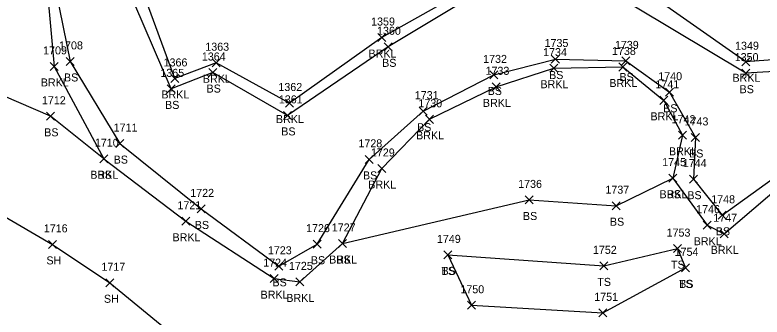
# Model space of a CAD drawing. Extents: x 1754529 to 1755810, y 621660 to 624656.
# Drawn here: x 1755027.6 to 1755214.3, y 623873.5 to 623948.9 of the extents above; entities that cross this region are included whole.
import ezdxf

# ---------------------------------------------------------------- set-up
doc = ezdxf.new("R2010")
doc.units = 0
for name, color, linetype in [('L_A', 7, 'Continuous'), ('L_I', 7, 'Continuous'), ('L_TIC', 7, 'Continuous'), ('LAWE', 7, 'Continuous'), ('LELB', 7, 'Continuous'), ('LSOGP', 7, 'Continuous')]:
    doc.layers.add(name, color=color, linetype=linetype)

msp = doc.modelspace()

# ---------------------------------------------------------------- linework, layer by layer
at = {"layer": 'L_TIC'}
for points in [[(1755118.33, 623942.27), (1755120.33, 623944.27)], [(1755120.33, 623942.27), (1755118.33, 623944.27)], [(1755119.93, 623939.96), (1755121.93, 623941.96)], [(1755121.93, 623939.96), (1755119.93, 623941.96)], [(1755040.45, 623936.31), (1755042.45, 623938.31)], [(1755042.45, 623936.31), (1755040.45, 623938.31)], [(1755076.94, 623935.98), (1755078.94, 623937.98)], [(1755078.94, 623935.98), (1755076.94, 623937.98)], [(1755161.66, 623936.91), (1755163.66, 623938.91)], [(1755163.66, 623936.91), (1755161.66, 623938.91)], [(1755179.24, 623936.43), (1755181.24, 623938.43)], [(1755181.24, 623936.43), (1755179.24, 623938.43)], [(1755209.27, 623936.23), (1755211.27, 623938.23)], [(1755211.27, 623936.23), (1755209.27, 623938.23)], [(1755036.46, 623935.07), (1755038.46, 623937.07)], [(1755038.46, 623935.07), (1755036.46, 623937.07)], [(1755076.07, 623933.54), (1755078.07, 623935.54)], [(1755078.07, 623933.54), (1755076.07, 623935.54)], [(1755161.29, 623934.63), (1755163.29, 623936.63)], [(1755163.29, 623934.63), (1755161.29, 623936.63)], [(1755178.51, 623934.92), (1755180.51, 623936.92)], [(1755180.51, 623934.92), (1755178.51, 623936.92)], [(1755209.26, 623933.38), (1755211.26, 623935.38)], [(1755211.26, 623933.38), (1755209.26, 623935.38)], [(1755066.58, 623932.06), (1755068.58, 623934.06)], [(1755068.58, 623932.06), (1755066.58, 623934.06)], [(1755146.31, 623932.94), (1755148.31, 623934.94)], [(1755148.31, 623932.94), (1755146.31, 623934.94)], [(1755146.91, 623929.97), (1755148.91, 623931.97)], [(1755148.91, 623929.97), (1755146.91, 623931.97)], [(1755065.71, 623929.46), (1755067.71, 623931.46)], [(1755067.71, 623929.46), (1755065.71, 623931.46)], [(1755190.16, 623928.62), (1755192.16, 623930.62)], [(1755192.16, 623928.62), (1755190.16, 623930.62)], [(1755095.2, 623925.93), (1755097.2, 623927.93)], [(1755097.2, 623925.93), (1755095.2, 623927.93)], [(1755188.79, 623926.6), (1755190.79, 623928.6)], [(1755190.79, 623926.6), (1755188.79, 623928.6)], [(1755035.51, 623922.62), (1755037.51, 623924.62)], [(1755037.51, 623922.62), (1755035.51, 623924.62)], [(1755094.74, 623922.84), (1755096.74, 623924.84)], [(1755096.74, 623922.84), (1755094.74, 623924.84)], [(1755128.67, 623923.89), (1755130.67, 623925.89)], [(1755130.67, 623923.89), (1755128.67, 623925.89)], [(1755130.22, 623921.86), (1755132.22, 623923.86)], [(1755132.22, 623921.86), (1755130.22, 623923.86)], [(1755193.4, 623917.88), (1755195.4, 623919.88)], [(1755195.4, 623917.88), (1755193.4, 623919.88)], [(1755196.64, 623917.34), (1755198.64, 623919.34)], [(1755198.64, 623917.34), (1755196.64, 623919.34)], [(1755052.86, 623915.81), (1755054.86, 623917.81)], [(1755054.86, 623915.81), (1755052.86, 623917.81)], [(1755048.82, 623912.03), (1755050.82, 623914.03)], [(1755050.82, 623912.03), (1755048.82, 623914.03)], [(1755048.82, 623912.03), (1755050.82, 623914.03)], [(1755050.82, 623912.03), (1755048.82, 623914.03)], [(1755115.15, 623911.87), (1755117.15, 623913.87)], [(1755117.15, 623911.87), (1755115.15, 623913.87)], [(1755118.28, 623909.59), (1755120.28, 623911.59)], [(1755120.28, 623909.59), (1755118.28, 623911.59)], [(1755191.05, 623907.18), (1755193.05, 623909.18)], [(1755193.05, 623907.18), (1755191.05, 623909.18)], [(1755191.05, 623907.18), (1755193.05, 623909.18)], [(1755193.05, 623907.18), (1755191.05, 623909.18)], [(1755196.2, 623906.93), (1755198.2, 623908.93)], [(1755198.2, 623906.93), (1755196.2, 623908.93)], [(1755155.12, 623901.74), (1755157.12, 623903.74)], [(1755157.12, 623901.74), (1755155.12, 623903.74)], [(1755176.86, 623900.31), (1755178.86, 623902.31)], [(1755178.86, 623900.31), (1755176.86, 623902.31)], [(1755073.13, 623899.5), (1755075.13, 623901.5)], [(1755075.13, 623899.5), (1755073.13, 623901.5)], [(1755203.31, 623897.91), (1755205.31, 623899.91)], [(1755205.31, 623897.91), (1755203.31, 623899.91)], [(1755069.37, 623896.42), (1755071.37, 623898.42)], [(1755071.37, 623896.42), (1755069.37, 623898.42)], [(1755199.59, 623895.44), (1755201.59, 623897.44)], [(1755201.59, 623895.44), (1755199.59, 623897.44)], [(1755203.82, 623893.29), (1755205.82, 623895.29)], [(1755205.82, 623893.29), (1755203.82, 623895.29)], [(1755036.03, 623890.65), (1755038.03, 623892.65)], [(1755038.03, 623890.65), (1755036.03, 623892.65)], [(1755102.13, 623890.7), (1755104.13, 623892.7)], [(1755104.13, 623890.7), (1755102.13, 623892.7)], [(1755108.49, 623890.87), (1755110.49, 623892.87)], [(1755110.49, 623890.87), (1755108.49, 623892.87)], [(1755108.49, 623890.87), (1755110.49, 623892.87)], [(1755110.49, 623890.87), (1755108.49, 623892.87)], [(1755192.16, 623889.59), (1755194.16, 623891.59)], [(1755194.16, 623889.59), (1755192.16, 623891.59)], [(1755134.78, 623888.03), (1755136.78, 623890.03)], [(1755136.78, 623888.03), (1755134.78, 623890.03)], [(1755134.78, 623888.03), (1755136.78, 623890.03)], [(1755136.78, 623888.03), (1755134.78, 623890.03)], [(1755092.54, 623885.18), (1755094.54, 623887.18)], [(1755094.54, 623885.18), (1755092.54, 623887.18)], [(1755173.74, 623885.29), (1755175.74, 623887.29)], [(1755175.74, 623885.29), (1755173.74, 623887.29)], [(1755194.16, 623884.79), (1755196.16, 623886.79)], [(1755196.16, 623884.79), (1755194.16, 623886.79)], [(1755194.16, 623884.79), (1755196.16, 623886.79)], [(1755196.16, 623884.79), (1755194.16, 623886.79)], [(1755050.38, 623881.08), (1755052.38, 623883.08)], [(1755052.38, 623881.08), (1755050.38, 623883.08)], [(1755091.38, 623882.1), (1755093.38, 623884.1)], [(1755093.38, 623882.1), (1755091.38, 623884.1)], [(1755097.8, 623881.29), (1755099.8, 623883.29)], [(1755099.8, 623881.29), (1755097.8, 623883.29)], [(1755140.72, 623875.45), (1755142.72, 623877.45)], [(1755142.72, 623875.45), (1755140.72, 623877.45)], [(1755173.5, 623873.56), (1755175.5, 623875.56)], [(1755175.5, 623873.56), (1755173.5, 623875.56)]]:
    msp.add_lwpolyline(points, dxfattribs=at)
at = {"layer": 'LAWE'}
for points in [[(1755170.6, 623960.85), (1755161.2, 623961.01), (1755143.2, 623956.78), (1755119.33, 623943.27), (1755096.2, 623926.93), (1755077.94, 623936.98), (1755067.58, 623933.06), (1755059.57, 623954.81), (1755059, 623978.5), (1755052.5, 623999.83), (1755039.74, 624025.98), (1755043.94, 624041.32), (1755011.46, 624067.07)], [(1755008.39, 624026.55), (1755031, 623998.61), (1755039.69, 623976.43), (1755035.65, 623955.37), (1755037.46, 623936.07), (1755049.82, 623913.03), (1755070.37, 623897.42), (1755092.38, 623883.1), (1755098.8, 623882.29), (1755109.49, 623891.87), (1755119.28, 623910.59), (1755131.22, 623922.86), (1755147.91, 623930.97), (1755162.29, 623935.63), (1755179.51, 623935.92), (1755189.79, 623927.6), (1755194.4, 623918.88), (1755192.05, 623908.18), (1755200.59, 623896.44), (1755204.82, 623894.29), (1755230.46, 623916.2)], [(1755370.87, 623791.95), (1755363.68, 623808), (1755365.74, 623820.69), (1755355.03, 623846.72), (1755346.68, 623853.51), (1755335.09, 623877.41), (1755323.56, 623896.77), (1755319.21, 623906.81), (1755286.2, 623944.29), (1755265.65, 623945.4), (1755241.6, 623939.51), (1755210.27, 623937.23), (1755179.93, 623958.52)]]:
    msp.add_lwpolyline(points, dxfattribs=at)
at = {"layer": 'LELB'}
for points in [[(1755241.68, 623936.2), (1755210.26, 623934.38), (1755173.74, 623956.25), (1755172.44, 623956.64), (1755160.09, 623957.64), (1755143.35, 623954.54), (1755120.93, 623940.96), (1755095.74, 623923.84), (1755077.07, 623934.54), (1755066.71, 623930.46), (1755055.52, 623956.39), (1755055.45, 623977.68), (1755049.43, 623997.7), (1755037.69, 624026.06), (1755041.22, 624040.25), (1755009.04, 624065.23)], [(1755012.46, 624027.69), (1755032.85, 623998.91), (1755041.63, 623976.49), (1755037.86, 623954.93), (1755041.45, 623937.31), (1755053.86, 623916.81), (1755074.13, 623900.5), (1755093.54, 623886.18), (1755103.13, 623891.7), (1755116.15, 623912.87), (1755129.67, 623924.89), (1755147.31, 623933.94), (1755162.66, 623937.91), (1755180.24, 623937.43), (1755191.16, 623929.62), (1755197.64, 623918.34), (1755197.2, 623907.93), (1755204.31, 623898.91), (1755229.99, 623917.44)], [(1755049.82, 623913.03), (1755036.51, 623923.62), (1754996.89, 623940.7), (1754976.92, 623965.01)], [(1755109.49, 623891.87), (1755156.12, 623902.74), (1755177.86, 623901.31), (1755192.05, 623908.18)], [(1755135.78, 623889.03), (1755174.74, 623886.29), (1755193.16, 623890.59), (1755195.16, 623885.79)], [(1755135.78, 623889.03), (1755141.72, 623876.45), (1755174.5, 623874.56), (1755195.16, 623885.79)]]:
    msp.add_lwpolyline(points, dxfattribs=at)
at = {"layer": 'LSOGP'}
msp.add_lwpolyline([(1755004.07, 623910.86), (1755037.03, 623891.65), (1755051.38, 623882.08), (1755070.03, 623866.74), (1755086.65, 623861.82), (1755098.54, 623857.57), (1755139.32, 623863.34), (1755161.91, 623859.08), (1755179.26, 623858.35), (1755194.19, 623862.7), (1755207.96, 623861.99), (1755217.43, 623865.11), (1755235.99, 623865.05), (1755250.43, 623863.91), (1755263.55, 623860.65), (1755279.26, 623833.69), (1755282.84, 623818.8), (1755283.41, 623777.57), (1755283.62, 623765.66), (1755287.66, 623764.84), (1755327.27, 623772.06), (1755352.63, 623769.93), (1755354.61, 623769.01), (1755434.62, 623771.42)], dxfattribs=at)

# ---------------------------------------------------------------- texts
at = {"layer": 'L_A'}
for s, p in [('BRKL', (1755115.98, 623938.27)), ('BS', (1755119.38, 623935.96)), ('BS', (1755039.89, 623932.31)), ('BRKL', (1755074.59, 623931.98)), ('BS', (1755161.1, 623932.91)), ('BS', (1755178.68, 623932.43)), ('BRKL', (1755206.92, 623932.23)), ('BRKL', (1755034.1, 623931.07)), ('BS', (1755075.51, 623929.54)), ('BRKL', (1755158.94, 623930.63)), ('BRKL', (1755176.16, 623930.92)), ('BRKL', (1755064.22, 623928.06)), ('BS', (1755145.75, 623928.94)), ('BS', (1755208.7, 623929.38)), ('BRKL', (1755144.56, 623925.97)), ('BS', (1755065.15, 623925.46)), ('BS', (1755189.6, 623924.62)), ('BRKL', (1755186.43, 623922.6)), ('BRKL', (1755092.85, 623921.93)), ('BS', (1755034.95, 623918.62)), ('BS', (1755094.18, 623918.84)), ('BS', (1755128.11, 623919.89)), ('BRKL', (1755127.87, 623917.86)), ('BRKL', (1755191.05, 623913.88)), ('BS', (1755196.08, 623913.34)), ('BS', (1755052.3, 623911.81)), ('BRKL', (1755046.47, 623908.03)), ('BS', (1755048.26, 623908.03)), ('BS', (1755114.6, 623907.87)), ('BRKL', (1755115.92, 623905.59)), ('BRKL', (1755188.69, 623903.18)), ('BS', (1755190.49, 623903.18)), ('BS', (1755195.64, 623902.93)), ('BS', (1755154.56, 623897.74)), ('BS', (1755176.3, 623896.31)), ('BS', (1755072.57, 623895.5)), ('BRKL', (1755067.01, 623892.42)), ('BS', (1755202.75, 623893.91)), ('BRKL', (1755197.24, 623891.44)), ('BRKL', (1755201.47, 623889.29)), ('SH', (1755035.51, 623886.65)), ('BS', (1755101.57, 623886.7)), ('BRKL', (1755106.14, 623886.87)), ('BS', (1755107.94, 623886.87)), ('TS', (1755191.57, 623885.59)), ('TS', (1755134.19, 623884.03)), ('BS', (1755134.23, 623884.03)), ('BS', (1755091.98, 623881.18)), ('TS', (1755173.15, 623881.29)), ('TS', (1755193.57, 623880.79)), ('BS', (1755193.6, 623880.79)), ('BRKL', (1755089.02, 623878.1)), ('BRKL', (1755095.44, 623877.29)), ('SH', (1755049.87, 623877.08))]:
    msp.add_text(s, height=2, dxfattribs=at).set_placement(p)
at = {"layer": 'L_I'}
for s, p in [('1359', (1755116.63, 623946.27)), ('1360', (1755118.11, 623943.96)), ('1735', (1755159.97, 623940.91)), ('1709', (1755034.68, 623939.07)), ('1708', (1755038.67, 623940.31)), ('1363', (1755075.2, 623939.98)), ('1738', (1755176.82, 623938.92)), ('1739', (1755177.54, 623940.43)), ('1349', (1755207.57, 623940.23)), ('1364', (1755074.33, 623937.54)), ('1732', (1755144.62, 623936.94)), ('1734', (1755159.6, 623938.63)), ('1350', (1755207.48, 623937.38)), ('1366', (1755064.78, 623936.06)), ('1365', (1755063.97, 623933.46)), ('1733', (1755145.22, 623933.97)), ('1740', (1755188.38, 623932.62)), ('1362', (1755093.46, 623929.93)), ('1741', (1755187.66, 623930.6)), ('1731', (1755127.54, 623927.89)), ('1712', (1755034.38, 623926.62)), ('1361', (1755093.57, 623926.84)), ('1730', (1755128.44, 623925.86)), ('1742', (1755191.71, 623921.88)), ('1743', (1755194.95, 623921.34)), ('1711', (1755052.3, 623919.81)), ('1710', (1755047.61, 623916.03)), ('1710', (1755047.61, 623916.03)), ('1728', (1755113.46, 623915.87)), ('1729', (1755116.58, 623913.59)), ('1745', (1755189.36, 623911.18)), ('1745', (1755189.36, 623911.18)), ('1744', (1755194.5, 623910.93)), ('1736', (1755153.37, 623905.74)), ('1722', (1755071.44, 623903.5)), ('1737', (1755175.17, 623904.31)), ('1748', (1755201.61, 623901.91)), ('1721', (1755068.24, 623900.42)), ('1746', (1755197.84, 623899.44)), ('1747', (1755202.13, 623897.29)), ('1716', (1755034.85, 623894.65)), ('1726', (1755100.38, 623894.7)), ('1727', (1755106.8, 623894.87)), ('1727', (1755106.8, 623894.87)), ('1753', (1755190.46, 623893.59)), ('1749', (1755133.08, 623892.03)), ('1749', (1755133.08, 623892.03)), ('1723', (1755090.84, 623889.18)), ('1752', (1755172.05, 623889.29)), ('1754', (1755192.47, 623888.79)), ('1754', (1755192.47, 623888.79)), ('1717', (1755049.25, 623885.08)), ('1724', (1755089.68, 623886.1)), ('1725', (1755096.1, 623885.29)), ('1750', (1755138.94, 623879.45)), ('1751', (1755172.38, 623877.56))]:
    msp.add_text(s, height=2, dxfattribs=at).set_placement(p)

doc.saveas('drawing.dxf')
